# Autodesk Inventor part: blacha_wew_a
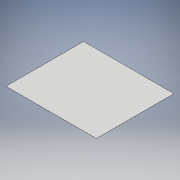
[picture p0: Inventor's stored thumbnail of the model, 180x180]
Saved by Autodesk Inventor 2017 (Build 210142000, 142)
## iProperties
Created: 2020-09
Part Number: blacha_wew_a
Material: Generic
Document SubType Name: Modeling
Designer: WindowsX
Density: 1 g/cm^3
Appearance: Default
Mass: 1644.15 g
Surface Area: 21985 cm^2
Volume: 1644.15 cm^3
Author: WindowsX
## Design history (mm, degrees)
sketch "Szkic1"
  geometry: L1 (0, 0)-(1130, 0); L2 (1130, 0)-(1130, 970); L3 (1130, 970)-(0, 970); L4 (0, 970)-(0, 0)
  constraints: 8 end point, 2 parallel, 1 horizontal, 1 perpendicular
  dimensions: "d0" = 1130 distance of L2.end L3.end; "d1" = 970 distance of L1.start L3.end
extrude "Wyciągnięcie proste1" new body sketch "Szkic1" distance "d2" = 1.5; taper "d3" = 0 deg
node "Bryła1"
